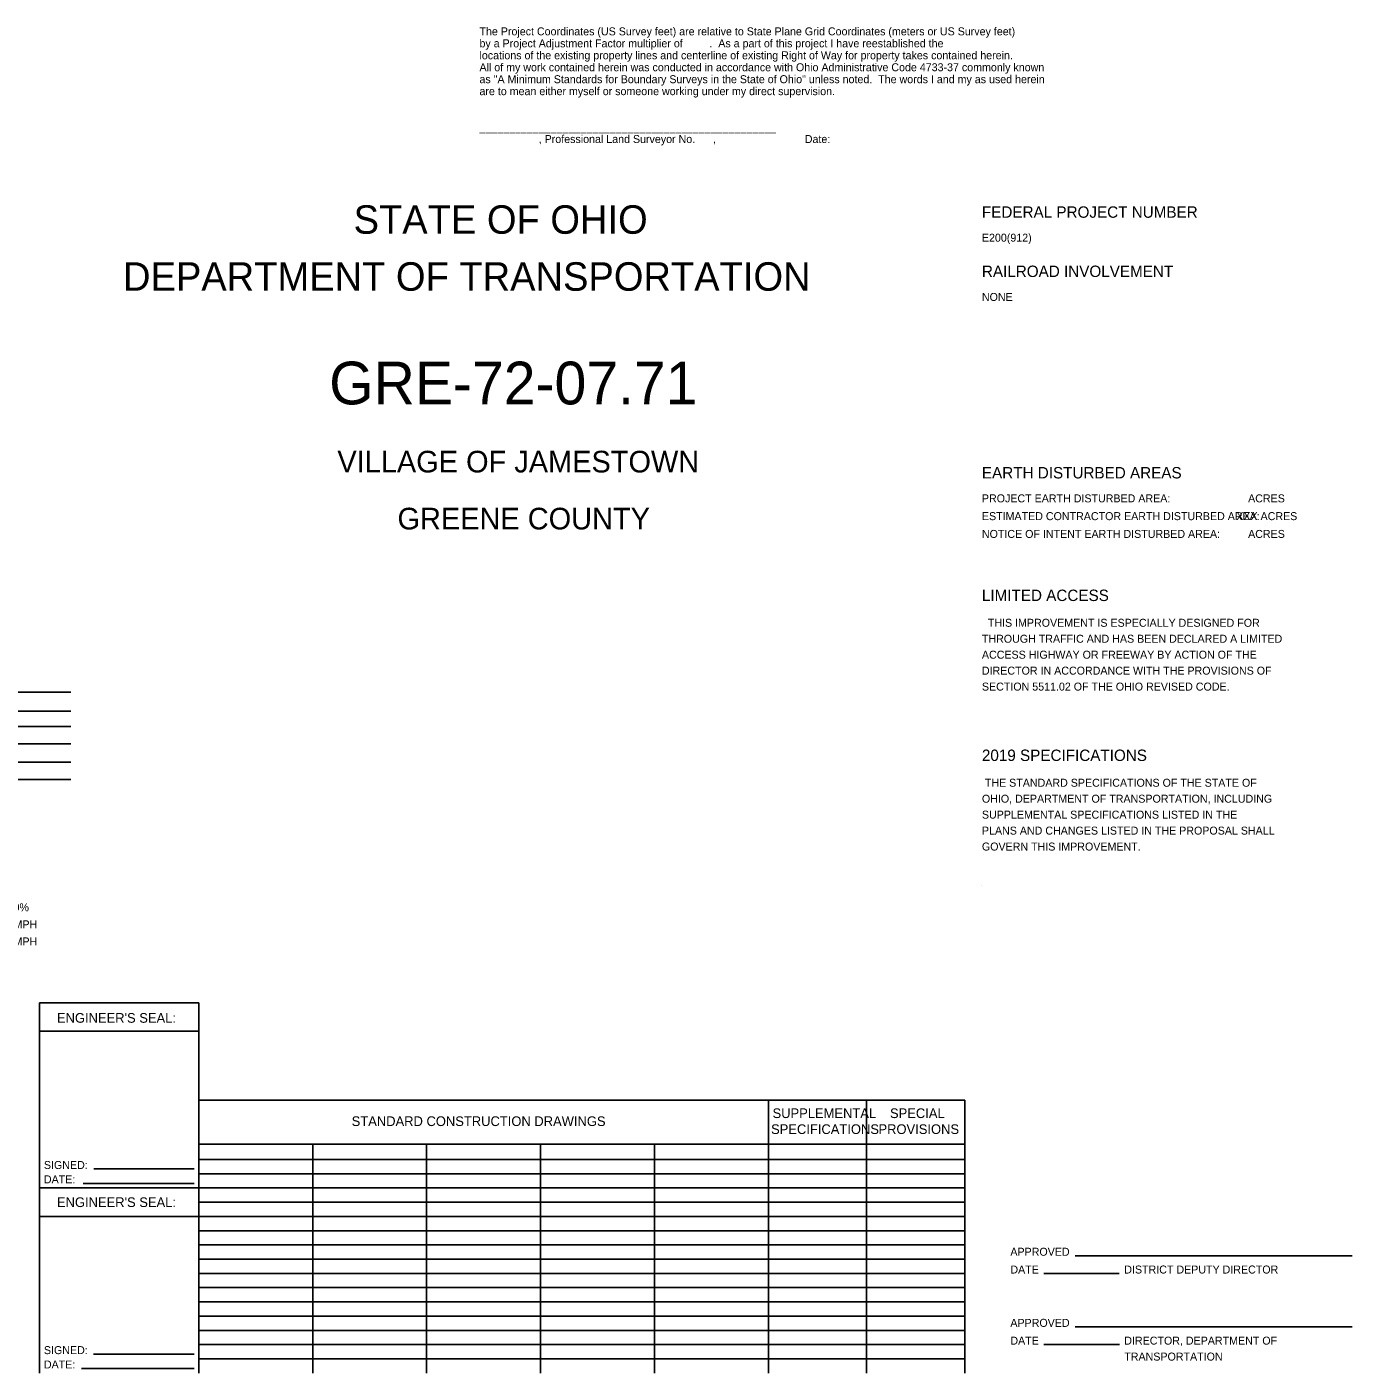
# Model space of a CAD drawing. Extents: x -13.9 to 69.1, y -25.2 to 26.1.
# Drawn here: x 7.96 to 31.23, y -25.19 to -1.56 of the extents above; entities that cross this region are included whole.
import ezdxf

# ---------------------------------------------------------------- set-up
doc = ezdxf.new("R2010")
doc.units = 0
doc.layers.add('SH_Data', color=7, linetype='Continuous')
doc.layers.add('SH_Text', color=7, linetype='Continuous')

msp = doc.modelspace()

# ---------------------------------------------------------------- linework, layer by layer
at = {"layer": 'SH_Data'}
for p, q in [((7.513, -13.231), (8.731, -13.231)), ((8.731, -13.566), (7.481, -13.566)), ((8.731, -13.838), (7.481, -13.838)), ((8.731, -14.138), (7.481, -14.138)), ((8.731, -14.464), (7.481, -14.464)), ((8.731, -14.764), (7.481, -14.764)), ((24.731, -16.626), (24.731, -16.626)), ((8.181, -21.937), (8.181, -18.687)), ((8.181, -18.687), (10.981, -18.687)), ((10.981, -25.187), (10.981, -18.687)), ((8.181, -19.187), (10.981, -19.187)), ((10.981, -20.395), (24.431, -20.395)), ((20.981, -25.187), (20.981, -20.395)), ((22.706, -25.187), (22.706, -20.395)), ((24.431, -25.187), (24.431, -20.395)), ((10.981, -21.166), (24.431, -21.166)), ((12.981, -25.187), (12.981, -21.166)), ((14.981, -25.187), (14.981, -21.166)), ((16.981, -25.187), (16.981, -21.166)), ((18.981, -25.187), (18.981, -21.166)), ((10.981, -21.437), (24.431, -21.437)), ((10.981, -21.687), (24.431, -21.687)), ((8.181, -25.187), (8.181, -21.937)), ((8.181, -21.937), (10.981, -21.937)), ((10.981, -21.937), (24.431, -21.937)), ((10.981, -22.187), (24.431, -22.187)), ((8.181, -22.437), (10.981, -22.437)), ((10.981, -22.437), (24.431, -22.437)), ((10.981, -22.687), (24.431, -22.687)), ((10.981, -22.937), (24.431, -22.937)), ((26.366, -23.127), (31.231, -23.127)), ((10.981, -23.187), (24.431, -23.187)), ((10.981, -23.437), (24.431, -23.437)), ((25.821, -23.439), (27.139, -23.439)), ((10.981, -23.687), (24.431, -23.687)), ((10.981, -23.937), (24.431, -23.937)), ((10.981, -24.187), (24.431, -24.187)), ((10.981, -24.437), (24.431, -24.437)), ((26.366, -24.375), (31.231, -24.375)), ((10.981, -24.687), (24.431, -24.687)), ((25.821, -24.687), (27.145, -24.687)), ((10.981, -24.937), (24.431, -24.937))]:
    msp.add_line(p, q, dxfattribs=at)
at = {"layer": 'SH_Text'}
for p, q in [((9.139, -21.604), (10.902, -21.604)), ((8.953, -21.856), (10.902, -21.856)), ((9.132, -24.854), (10.902, -24.854)), ((8.924, -25.106), (10.902, -25.106))]:
    msp.add_line(p, q, dxfattribs=at)

# ---------------------------------------------------------------- texts
for s, height, p in [('The Project Coordinates (US Survey feet) are relative to State Plane Grid Coordinates (meters or US Survey feet)', 0.14, (15.909, -1.704)), ('by a Project Adjustment Factor multiplier of         .  As a part of this project I have reestablished the', 0.14, (15.909, -1.914)), ('locations of the existing property lines and centerline of existing Right of Way for property takes contained herein.  ', 0.14, (15.909, -2.124)), ('All of my work contained herein was conducted in accordance with Ohio Administrative Code 4733-37 commonly known', 0.14, (15.909, -2.334)), ('as "A Minimum Standards for Boundary Surveys in the State of Ohio" unless noted.  The words I and my as used herein', 0.14, (15.909, -2.544)), ('are to mean either myself or someone working under my direct supervision.', 0.14, (15.909, -2.754)), ('__________________________________________________', 0.14, (15.909, -3.384)), ('                    , Professional Land Surveyor No.      ,                              Date:                ', 0.14, (15.909, -3.594)), ('STATE OF OHIO', 0.5, (13.699, -5.187)), ('FEDERAL PROJECT NUMBER', 0.2, (24.731, -4.906)), ('E200(912)', 0.14, (24.731, -5.326)), ('DEPARTMENT OF TRANSPORTATION', 0.5, (9.65, -6.187)), ('RAILROAD INVOLVEMENT', 0.2, (24.731, -5.946)), ('NONE', 0.14, (24.731, -6.366)), ('GRE-72-07.71', 0.75, (13.27, -8.182)), ('VILLAGE OF JAMESTOWN', 0.38, (13.414, -9.377)), ('EARTH DISTURBED AREAS', 0.2, (24.731, -9.482)), ('PROJECT EARTH DISTURBED AREA:', 0.14, (24.731, -9.902)), ('     ACRES', 0.14, (29.145, -9.902)), ('    GREENE COUNTY   ', 0.38, (13.905, -10.377)), ('ESTIMATED CONTRACTOR EARTH DISTURBED AREA:', 0.14, (24.731, -10.214)), (' XXX ACRES', 0.14, (29.145, -10.214)), ('NOTICE OF INTENT EARTH DISTURBED AREA:', 0.14, (24.731, -10.526)), ('     ACRES', 0.14, (29.145, -10.526)), ('LIMITED ACCESS', 0.2, (24.731, -11.634)), ('  THIS IMPROVEMENT IS ESPECIALLY DESIGNED FOR', 0.14, (24.731, -12.086)), ('THROUGH TRAFFIC AND HAS BEEN DECLARED A LIMITED', 0.14, (24.731, -12.366)), ('ACCESS HIGHWAY OR FREEWAY BY ACTION OF THE', 0.14, (24.731, -12.646)), ('DIRECTOR IN ACCORDANCE WITH THE PROVISIONS OF', 0.14, (24.731, -12.926)), ('SECTION 5511.02 OF THE OHIO REVISED CODE.', 0.14, (24.731, -13.206)), ('2019 SPECIFICATIONS', 0.2, (24.731, -14.442)), (' THE STANDARD SPECIFICATIONS OF THE STATE OF', 0.14, (24.731, -14.894)), ('OHIO, DEPARTMENT OF TRANSPORTATION, INCLUDING', 0.14, (24.731, -15.174)), ('SUPPLEMENTAL SPECIFICATIONS LISTED IN THE', 0.14, (24.731, -15.454)), ('PLANS AND CHANGES LISTED IN THE PROPOSAL SHALL', 0.14, (24.731, -15.734)), ('GOVERN THIS IMPROVEMENT.', 0.14, (24.731, -16.014)), ('6.00%', 0.14, (7.468, -17.08)), ('35 MPH', 0.14, (7.468, -17.38)), ('35 MPH', 0.14, (7.468, -17.68)), ("ENGINEER'S SEAL:", 0.17, (8.49, -19.037)), ('SUPPLEMENTAL', 0.17, (21.055, -20.71)), ('SPECIAL', 0.17, (23.117, -20.71)), ('STANDARD CONSTRUCTION DRAWINGS', 0.17, (13.665, -20.85)), ('SPECIFICATIONS', 0.17, (21.029, -20.99)), ('PROVISIONS', 0.17, (22.915, -20.99)), ('SIGNED:', 0.14, (8.261, -21.604)), ('DATE:', 0.14, (8.261, -21.856)), ("ENGINEER'S SEAL:", 0.17, (8.49, -22.272)), ('APPROVED', 0.14, (25.231, -23.127)), ('DATE', 0.14, (25.231, -23.439)), ('DISTRICT DEPUTY DIRECTOR', 0.14, (27.231, -23.439)), ('APPROVED', 0.14, (25.231, -24.375)), ('DATE', 0.14, (25.231, -24.687)), ('DIRECTOR, DEPARTMENT OF', 0.14, (27.231, -24.687)), ('SIGNED:', 0.14, (8.261, -24.854)), ('DATE:', 0.14, (8.261, -25.106)), ('TRANSPORTATION', 0.14, (27.231, -24.967))]:
    msp.add_text(s, height=height, dxfattribs=at).set_placement(p)

doc.saveas('drawing.dxf')
